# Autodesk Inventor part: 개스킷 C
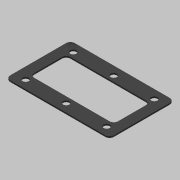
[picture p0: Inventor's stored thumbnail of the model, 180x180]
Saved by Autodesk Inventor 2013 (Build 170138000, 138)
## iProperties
Created: 2020-04
Part Number: 개스킷 C
Material: 고무
Document SubType Name: Modeling
Designer: mduedu
Density: 1 g/cm^3
Author: mduedu
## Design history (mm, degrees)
sketch "스케치1"
  geometry: L1 (37, 23)-(-37, 23); L2 (-37, 23)-(-37, -23); L3 (-37, -23)-(37, -23); L4 (37, -23)-(37, 23); L5 (37, 23)-(-37, -23); L6 (-37, 23)-(37, -23); L7 (30, 13)-(-30, 13); L8 (-30, 13)-(-30, -13); L9 (-30, -13)-(30, -13); L10 (30, -13)-(30, 13); L11 (30, 13)-(-30, -13); L12 (-30, 13)-(30, -13); 1 further point
  constraints: 24 end point, 4 midpoint, 4 parallel, 2 horizontal, 2 perpendicular
  dimensions: "d0" = 74 distance of L3.end L2.end; "d1" = 46 distance of L2.end L1.end; "d2" = 60 distance of L9.end L8.end; "d3" = 26 distance of L8.end L7.end
extrude "돌출1" new body sketch "스케치1" distance "d4" = 1; taper "d5" = 0 deg
fillet "모깎기1" dims "d6" = 3
fillet "모깎기2" dims "d7" = 3
sketch "스케치2"
  geometry: L1 (-29, -17)-(29, -17); L2 (29, -17)-(29, 17); L3 (29, 17)-(-29, 17); L4 (-29, 17)-(-29, -17); L5 (-29, -17)-(29, 17); L6 (29, -17)-(-29, 17); 7 further points
  constraints: 12 end point, 4 coincident, 4 midpoint, 2 parallel, 1 horizontal, 1 perpendicular
  dimensions: "d8" = 58 distance of L3.end L2.end; "d9" = 34 distance of L2.end L1.end
hole "구멍1" sketch "스케치2" at (-29, 17), (29, 17), (29, -17), (-29, -17), (0, 17), (0, -17) diameter "d10" = 4.5; stored, may be unused: countersink angle "d14" = 90 deg, drill point angle "d16" = 118 deg; dims "d11" = 6, "d12" = 4, "d13" = 2, "d15" = 8
node "솔리드1"
